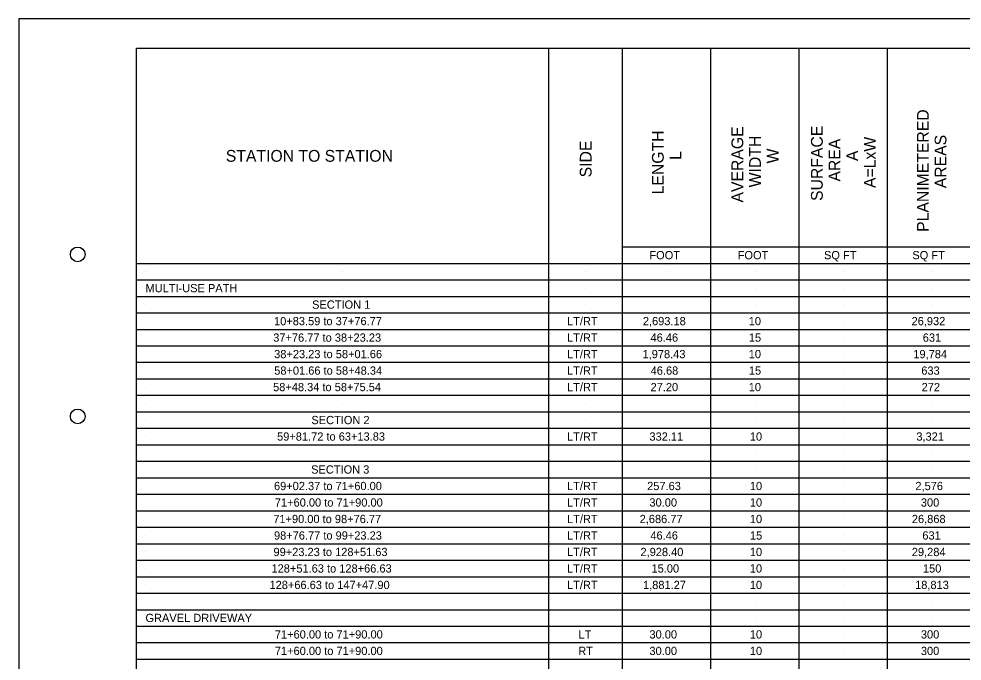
# Model space of a CAD drawing. Extents: x 2107022.8 to 2107056.8, y 706071 to 706093.
# Drawn here: x 2107022.81 to 2107038.83, y 706082.08 to 706092.99 of the extents above; entities that cross this region are included whole.
import ezdxf

# ---------------------------------------------------------------- set-up
doc = ezdxf.new("R2010")
doc.units = 0
for name, color, linetype in [('SC_Scratch1', 7, 'Continuous'), ('SH_Border', 7, 'Continuous'), ('SH_Cut_Line', 7, 'Continuous'), ('SH_Data', 7, 'Continuous'), ('SH_Text', 7, 'Continuous')]:
    doc.layers.add(name, color=color, linetype=linetype)

msp = doc.modelspace()

# ---------------------------------------------------------------- linework, layer by layer
at = {"layer": 'SC_Scratch1'}
for p, q in [((2107033.812, 706088.975), (2107033.812, 706088.975)), ((2107035.312, 706088.975), (2107035.312, 706088.975)), ((2107036.812, 706088.975), (2107036.812, 706088.975)), ((2107038.312, 706088.975), (2107038.312, 706088.975)), ((2107024.962, 706088.695), (2107024.962, 706088.695)), ((2107028.312, 706088.695), (2107028.312, 706088.695)), ((2107032.437, 706088.695), (2107032.437, 706088.695)), ((2107033.812, 706088.695), (2107033.812, 706088.695)), ((2107035.312, 706088.695), (2107035.312, 706088.695)), ((2107036.812, 706088.695), (2107036.812, 706088.695)), ((2107038.312, 706088.695), (2107038.312, 706088.695)), ((2107024.962, 706088.415), (2107024.962, 706088.415)), ((2107028.312, 706088.415), (2107028.312, 706088.415)), ((2107032.437, 706088.415), (2107032.437, 706088.415)), ((2107033.812, 706088.415), (2107033.812, 706088.415)), ((2107035.312, 706088.415), (2107035.312, 706088.415)), ((2107036.812, 706088.415), (2107036.812, 706088.415)), ((2107038.312, 706088.415), (2107038.312, 706088.415)), ((2107024.962, 706088.135), (2107024.962, 706088.135)), ((2107028.312, 706088.135), (2107028.312, 706088.135)), ((2107032.437, 706088.135), (2107032.437, 706088.135)), ((2107033.812, 706088.135), (2107033.812, 706088.135)), ((2107035.312, 706088.135), (2107035.312, 706088.135)), ((2107036.812, 706088.135), (2107036.812, 706088.135)), ((2107038.312, 706088.135), (2107038.312, 706088.135)), ((2107024.962, 706087.855), (2107024.962, 706087.855)), ((2107028.312, 706087.855), (2107028.312, 706087.855)), ((2107032.437, 706087.855), (2107032.437, 706087.855)), ((2107033.812, 706087.855), (2107033.812, 706087.855)), ((2107035.312, 706087.855), (2107035.312, 706087.855)), ((2107036.812, 706087.855), (2107036.812, 706087.855)), ((2107038.312, 706087.855), (2107038.312, 706087.855)), ((2107024.962, 706087.575), (2107024.962, 706087.575)), ((2107028.312, 706087.575), (2107028.312, 706087.575)), ((2107032.437, 706087.575), (2107032.437, 706087.575)), ((2107033.812, 706087.575), (2107033.812, 706087.575)), ((2107035.312, 706087.575), (2107035.312, 706087.575)), ((2107036.812, 706087.575), (2107036.812, 706087.575)), ((2107038.312, 706087.575), (2107038.312, 706087.575)), ((2107024.962, 706087.295), (2107024.962, 706087.295)), ((2107028.312, 706087.295), (2107028.312, 706087.295)), ((2107032.437, 706087.295), (2107032.437, 706087.295)), ((2107033.812, 706087.295), (2107033.812, 706087.295)), ((2107035.312, 706087.295), (2107035.312, 706087.295)), ((2107036.812, 706087.295), (2107036.812, 706087.295)), ((2107038.312, 706087.295), (2107038.312, 706087.295)), ((2107024.962, 706087.015), (2107024.962, 706087.015)), ((2107028.312, 706087.015), (2107028.312, 706087.015)), ((2107032.437, 706087.015), (2107032.437, 706087.015)), ((2107033.812, 706087.015), (2107033.812, 706087.015)), ((2107035.312, 706087.015), (2107035.312, 706087.015)), ((2107036.812, 706087.015), (2107036.812, 706087.015)), ((2107038.312, 706087.015), (2107038.312, 706087.015)), ((2107024.962, 706086.735), (2107024.962, 706086.735)), ((2107028.312, 706086.735), (2107028.312, 706086.735)), ((2107032.437, 706086.735), (2107032.437, 706086.735)), ((2107033.812, 706086.735), (2107033.812, 706086.735)), ((2107035.312, 706086.735), (2107035.312, 706086.735)), ((2107036.812, 706086.735), (2107036.812, 706086.735)), ((2107038.312, 706086.735), (2107038.312, 706086.735)), ((2107024.962, 706086.455), (2107024.962, 706086.455)), ((2107028.312, 706086.455), (2107028.312, 706086.455)), ((2107032.437, 706086.455), (2107032.437, 706086.455)), ((2107033.812, 706086.455), (2107033.812, 706086.455)), ((2107035.312, 706086.455), (2107035.312, 706086.455)), ((2107036.812, 706086.455), (2107036.812, 706086.455)), ((2107038.312, 706086.455), (2107038.312, 706086.455)), ((2107024.962, 706086.175), (2107024.962, 706086.175)), ((2107028.312, 706086.175), (2107028.312, 706086.175)), ((2107032.437, 706086.175), (2107032.437, 706086.175)), ((2107033.812, 706086.175), (2107033.812, 706086.175)), ((2107035.312, 706086.175), (2107035.312, 706086.175)), ((2107036.812, 706086.175), (2107036.812, 706086.175)), ((2107038.312, 706086.175), (2107038.312, 706086.175)), ((2107024.962, 706085.895), (2107024.962, 706085.895)), ((2107028.312, 706085.895), (2107028.312, 706085.895)), ((2107032.437, 706085.895), (2107032.437, 706085.895)), ((2107033.812, 706085.895), (2107033.812, 706085.895)), ((2107035.312, 706085.895), (2107035.312, 706085.895)), ((2107036.812, 706085.895), (2107036.812, 706085.895)), ((2107038.312, 706085.895), (2107038.312, 706085.895)), ((2107024.962, 706085.615), (2107024.962, 706085.615)), ((2107028.312, 706085.615), (2107028.312, 706085.615)), ((2107032.437, 706085.615), (2107032.437, 706085.615)), ((2107033.812, 706085.615), (2107033.812, 706085.615)), ((2107035.312, 706085.615), (2107035.312, 706085.615)), ((2107036.812, 706085.615), (2107036.812, 706085.615)), ((2107038.312, 706085.615), (2107038.312, 706085.615)), ((2107024.962, 706085.335), (2107024.962, 706085.335)), ((2107028.312, 706085.335), (2107028.312, 706085.335)), ((2107032.437, 706085.335), (2107032.437, 706085.335)), ((2107033.812, 706085.335), (2107033.812, 706085.335)), ((2107035.312, 706085.335), (2107035.312, 706085.335)), ((2107036.812, 706085.335), (2107036.812, 706085.335)), ((2107038.312, 706085.335), (2107038.312, 706085.335)), ((2107024.962, 706085.055), (2107024.962, 706085.055)), ((2107028.312, 706085.055), (2107028.312, 706085.055)), ((2107032.437, 706085.055), (2107032.437, 706085.055)), ((2107033.812, 706085.055), (2107033.812, 706085.055)), ((2107035.312, 706085.055), (2107035.312, 706085.055)), ((2107036.812, 706085.055), (2107036.812, 706085.055)), ((2107038.312, 706085.055), (2107038.312, 706085.055)), ((2107024.962, 706084.775), (2107024.962, 706084.775)), ((2107028.312, 706084.775), (2107028.312, 706084.775)), ((2107032.437, 706084.775), (2107032.437, 706084.775)), ((2107033.812, 706084.775), (2107033.812, 706084.775)), ((2107035.312, 706084.775), (2107035.312, 706084.775)), ((2107036.812, 706084.775), (2107036.812, 706084.775)), ((2107038.312, 706084.775), (2107038.312, 706084.775)), ((2107024.962, 706084.495), (2107024.962, 706084.495)), ((2107028.312, 706084.495), (2107028.312, 706084.495)), ((2107032.437, 706084.495), (2107032.437, 706084.495)), ((2107033.812, 706084.495), (2107033.812, 706084.495)), ((2107035.312, 706084.495), (2107035.312, 706084.495)), ((2107036.812, 706084.495), (2107036.812, 706084.495)), ((2107038.312, 706084.495), (2107038.312, 706084.495)), ((2107024.962, 706084.215), (2107024.962, 706084.215)), ((2107028.312, 706084.215), (2107028.312, 706084.215)), ((2107032.437, 706084.215), (2107032.437, 706084.215)), ((2107033.812, 706084.215), (2107033.812, 706084.215)), ((2107035.312, 706084.215), (2107035.312, 706084.215)), ((2107036.812, 706084.215), (2107036.812, 706084.215)), ((2107038.312, 706084.215), (2107038.312, 706084.215)), ((2107024.962, 706083.935), (2107024.962, 706083.935)), ((2107028.312, 706083.935), (2107028.312, 706083.935)), ((2107032.437, 706083.935), (2107032.437, 706083.935)), ((2107033.812, 706083.935), (2107033.812, 706083.935)), ((2107035.312, 706083.935), (2107035.312, 706083.935)), ((2107036.812, 706083.935), (2107036.812, 706083.935)), ((2107038.312, 706083.935), (2107038.312, 706083.935)), ((2107024.962, 706083.655), (2107024.962, 706083.655)), ((2107028.312, 706083.655), (2107028.312, 706083.655)), ((2107032.437, 706083.655), (2107032.437, 706083.655)), ((2107033.812, 706083.655), (2107033.812, 706083.655)), ((2107035.312, 706083.655), (2107035.312, 706083.655)), ((2107036.812, 706083.655), (2107036.812, 706083.655)), ((2107038.312, 706083.655), (2107038.312, 706083.655)), ((2107024.962, 706083.375), (2107024.962, 706083.375)), ((2107028.312, 706083.375), (2107028.312, 706083.375)), ((2107032.437, 706083.375), (2107032.437, 706083.375)), ((2107033.812, 706083.375), (2107033.812, 706083.375)), ((2107035.312, 706083.375), (2107035.312, 706083.375)), ((2107036.812, 706083.375), (2107036.812, 706083.375)), ((2107038.312, 706083.375), (2107038.312, 706083.375)), ((2107024.962, 706083.095), (2107024.962, 706083.095)), ((2107028.312, 706083.095), (2107028.312, 706083.095)), ((2107032.437, 706083.095), (2107032.437, 706083.095)), ((2107033.812, 706083.095), (2107033.812, 706083.095)), ((2107035.312, 706083.095), (2107035.312, 706083.095)), ((2107036.812, 706083.095), (2107036.812, 706083.095)), ((2107038.312, 706083.095), (2107038.312, 706083.095)), ((2107024.962, 706082.815), (2107024.962, 706082.815)), ((2107028.312, 706082.815), (2107028.312, 706082.815)), ((2107032.437, 706082.815), (2107032.437, 706082.815)), ((2107033.812, 706082.815), (2107033.812, 706082.815)), ((2107035.312, 706082.815), (2107035.312, 706082.815)), ((2107036.812, 706082.815), (2107036.812, 706082.815)), ((2107038.312, 706082.815), (2107038.312, 706082.815)), ((2107024.962, 706082.535), (2107024.962, 706082.535)), ((2107028.312, 706082.535), (2107028.312, 706082.535)), ((2107032.437, 706082.535), (2107032.437, 706082.535)), ((2107033.812, 706082.535), (2107033.812, 706082.535)), ((2107035.312, 706082.535), (2107035.312, 706082.535)), ((2107036.812, 706082.535), (2107036.812, 706082.535)), ((2107038.312, 706082.535), (2107038.312, 706082.535)), ((2107024.962, 706082.255), (2107024.962, 706082.255)), ((2107028.312, 706082.255), (2107028.312, 706082.255)), ((2107032.437, 706082.255), (2107032.437, 706082.255)), ((2107033.812, 706082.255), (2107033.812, 706082.255)), ((2107035.312, 706082.255), (2107035.312, 706082.255)), ((2107036.812, 706082.255), (2107036.812, 706082.255)), ((2107038.312, 706082.255), (2107038.312, 706082.255))]:
    msp.add_line(p, q, dxfattribs=at)
at = {"layer": 'SH_Border'}
msp.add_lwpolyline([(2107024.812, 706092.487), (2107056.312, 706092.487), (2107056.312, 706071.487), (2107024.812, 706071.487)], close=True, dxfattribs=at)
for centre in [(2107023.812, 706088.987), (2107023.812, 706086.237)]:
    msp.add_circle(centre, 0.125, dxfattribs=at)
at = {"layer": 'SH_Cut_Line'}
msp.add_lwpolyline([(2107022.812, 706070.987), (2107056.812, 706070.987), (2107056.812, 706092.987), (2107022.812, 706092.987)], close=True, dxfattribs=at)
at = {"layer": 'SH_Data'}
for p, q in [((2107031.812, 706072.035), (2107031.812, 706092.487)), ((2107033.062, 706072.035), (2107033.062, 706092.487)), ((2107034.562, 706072.035), (2107034.562, 706092.487)), ((2107036.062, 706072.035), (2107036.062, 706092.487)), ((2107037.562, 706072.035), (2107037.562, 706092.487)), ((2107033.062, 706089.115), (2107055.312, 706089.115)), ((2107024.812, 706088.835), (2107055.312, 706088.835)), ((2107024.812, 706088.555), (2107055.312, 706088.555)), ((2107024.812, 706088.275), (2107055.312, 706088.275)), ((2107024.812, 706087.995), (2107055.312, 706087.995)), ((2107024.812, 706087.715), (2107055.312, 706087.715)), ((2107024.812, 706087.435), (2107055.312, 706087.435)), ((2107024.812, 706087.155), (2107055.312, 706087.155)), ((2107024.812, 706086.875), (2107055.312, 706086.875)), ((2107024.812, 706086.595), (2107055.312, 706086.595)), ((2107024.812, 706086.315), (2107055.312, 706086.315)), ((2107024.812, 706086.035), (2107055.312, 706086.035)), ((2107024.812, 706085.755), (2107055.312, 706085.755)), ((2107024.812, 706085.475), (2107055.312, 706085.475)), ((2107024.812, 706085.195), (2107055.312, 706085.195)), ((2107024.812, 706084.915), (2107055.312, 706084.915)), ((2107024.812, 706084.635), (2107055.312, 706084.635)), ((2107024.812, 706084.355), (2107055.312, 706084.355)), ((2107024.812, 706084.075), (2107055.312, 706084.075)), ((2107024.812, 706083.795), (2107055.312, 706083.795)), ((2107024.812, 706083.515), (2107055.312, 706083.515)), ((2107024.812, 706083.235), (2107055.312, 706083.235)), ((2107024.812, 706082.955), (2107055.312, 706082.955)), ((2107024.812, 706082.675), (2107055.312, 706082.675)), ((2107024.812, 706082.395), (2107055.312, 706082.395)), ((2107024.812, 706082.115), (2107055.312, 706082.115))]:
    msp.add_line(p, q, dxfattribs=at)

# ---------------------------------------------------------------- texts
for s, p in [('PLANIMETERED', (2107038.262, 706089.37)), ('AVERAGE', (2107035.112, 706089.868)), ('SURFACE', (2107036.462, 706089.895)), ('LENGTH', (2107033.762, 706090.007)), ('WIDTH', (2107035.412, 706090.126)), ('A=LxW', (2107037.362, 706090.115)), ('AREAS', (2107038.562, 706090.111)), ('SIDE', (2107032.537, 706090.296)), ('AREA', (2107036.762, 706090.224)), ('L', (2107034.062, 706090.592)), ('W', (2107035.712, 706090.532)), ('A', (2107037.062, 706090.572))]:
    msp.add_text(s, height=0.2, rotation=90, dxfattribs=at).set_placement(p)
msp.add_text('STATION TO STATION', height=0.2, dxfattribs=at).set_placement((2107026.326, 706090.561))
at = {"layer": 'SH_Text'}
for s, p in [('FOOT', (2107033.518, 706088.905)), ('FOOT', (2107035.018, 706088.905)), ('SQ FT', (2107036.483, 706088.905)), ('SQ FT', (2107037.983, 706088.905)), ('MULTI-USE PATH', (2107024.962, 706088.345)), ('SECTION 1', (2107027.791, 706088.065)), ('10+83.59 to 37+76.77', (2107027.145, 706087.785)), ('LT/RT', (2107032.12, 706087.785)), ('2,693.18', (2107033.407, 706087.785)), ('10', (2107035.205, 706087.785)), ('26,932', (2107037.97, 706087.785)), ('37+76.77 to 38+23.23', (2107027.131, 706087.505)), ('LT/RT', (2107032.12, 706087.505)), ('46.46', (2107033.537, 706087.505)), ('15', (2107035.207, 706087.505)), ('631', (2107038.16, 706087.505)), ('38+23.23 to 58+01.66', (2107027.147, 706087.225)), ('LT/RT', (2107032.12, 706087.225)), ('1,978.43', (2107033.402, 706087.225)), ('10', (2107035.205, 706087.225)), ('19,784', (2107038, 706087.225)), ('58+01.66 to 58+48.34', (2107027.148, 706086.945)), ('LT/RT', (2107032.12, 706086.945)), ('46.68', (2107033.54, 706086.945)), ('15', (2107035.207, 706086.945)), ('633', (2107038.135, 706086.945)), ('58+48.34 to 58+75.54', (2107027.129, 706086.665)), ('LT/RT', (2107032.12, 706086.665)), ('27.20', (2107033.538, 706086.665)), ('10', (2107035.205, 706086.665)), ('272', (2107038.141, 706086.665)), ('SECTION 2', (2107027.779, 706086.105)), ('59+81.72 to 63+13.83', (2107027.197, 706085.825)), ('LT/RT', (2107032.12, 706085.825)), ('332.11', (2107033.519, 706085.825)), ('10', (2107035.224, 706085.825)), ('3,321', (2107038.051, 706085.825)), ('SECTION 3', (2107027.775, 706085.265)), ('69+02.37 to 71+60.00', (2107027.144, 706084.985)), ('LT/RT', (2107032.12, 706084.985)), ('257.63', (2107033.48, 706084.985)), ('10', (2107035.224, 706084.985)), ('2,576', (2107038.035, 706084.985)), ('71+60.00 to 71+90.00', (2107027.159, 706084.705)), ('LT/RT', (2107032.12, 706084.705)), ('30.00', (2107033.519, 706084.705)), ('10', (2107035.224, 706084.705)), ('300', (2107038.128, 706084.705)), ('71+90.00 to 98+76.77', (2107027.132, 706084.425)), ('LT/RT', (2107032.12, 706084.425)), ('2,686.77', (2107033.353, 706084.425)), ('10', (2107035.224, 706084.425)), ('26,868', (2107037.975, 706084.425)), ('98+76.77 to 99+23.23', (2107027.144, 706084.145)), ('LT/RT', (2107032.12, 706084.145)), ('46.46', (2107033.535, 706084.145)), ('15', (2107035.226, 706084.145)), ('631', (2107038.153, 706084.145)), ('99+23.23 to 128+51.63', (2107027.136, 706083.865)), ('LT/RT', (2107032.12, 706083.865)), ('2,928.40', (2107033.367, 706083.865)), ('10', (2107035.224, 706083.865)), ('29,284', (2107037.974, 706083.865)), ('128+51.63 to 128+66.63', (2107027.102, 706083.585)), ('LT/RT', (2107032.12, 706083.585)), ('15.00', (2107033.554, 706083.585)), ('10', (2107035.224, 706083.585)), ('150', (2107038.163, 706083.585)), ('128+66.63 to 147+47.90', (2107027.068, 706083.305)), ('LT/RT', (2107032.12, 706083.305)), ('1,881.27', (2107033.41, 706083.305)), ('10', (2107035.224, 706083.305)), ('18,813', (2107038.03, 706083.305)), ('GRAVEL DRIVEWAY', (2107024.962, 706082.745)), ('71+60.00 to 71+90.00', (2107027.159, 706082.465)), ('LT', (2107032.315, 706082.465)), ('30.00', (2107033.519, 706082.465)), ('10', (2107035.224, 706082.465)), ('300', (2107038.128, 706082.465)), ('71+60.00 to 71+90.00', (2107027.159, 706082.185)), ('RT', (2107032.311, 706082.185)), ('30.00', (2107033.519, 706082.185)), ('10', (2107035.224, 706082.185)), ('300', (2107038.128, 706082.185))]:
    msp.add_text(s, height=0.14, dxfattribs=at).set_placement(p)

doc.saveas('drawing.dxf')
